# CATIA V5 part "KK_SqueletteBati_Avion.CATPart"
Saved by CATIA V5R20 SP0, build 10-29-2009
Part number: Squelette_bati_(avion)
Bounding box of the stored display mesh (mm): x -2696 to 0, y -488 to 1576, z -320 to 600
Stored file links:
  G:\Khaled_CFAO_2011\ST2M\ST2M_GR2\aboulegue\Khaled\CAD_thinkMOTION\KK_SqueletteBati_Avion.CATPart
  G:\Khaled_CFAO_2011\ST2M\ST2M_GR2\aboulegue\Khaled\CAD_thinkMOTION\KK_Train_Atterrissage.CATProduct
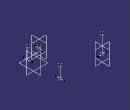
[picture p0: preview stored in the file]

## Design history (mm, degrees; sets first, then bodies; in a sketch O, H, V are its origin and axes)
Set1
  Point1 "Point.25": linked copy from another document
  Point2 "Point.22": linked copy from another document
  Point3 "Point.26": linked copy from another document
  Point4 "Point.23": linked copy from another document
  Point5 "Point.24": linked copy from another document
  Point6 "Point.11": linked copy from another document
  Plane1 "Plan reference 2": linked copy from another document
  Point7 "Point.27": linked copy from another document
  Point8 "Point.18": linked copy from another document
  Plane2 "Plan reference": linked copy from another document
Set2 "Set bati (avion)"
  Line1: type PtPt, FirstPoint Point1, SecondPoint Point2
  Line2: type PtPt, FirstPoint Point3, SecondPoint Point4
  Line3: type PtPt, FirstPoint Point5, SecondPoint Point6
  Line4: type Normal, RefPoint Point6, RefSkin Plane1, Start -200, End 200
  Line5: type Normal, RefPoint Point2, RefSkin Plane1, Start -200, End 200
  Line6: type Normal, RefPoint Point4, RefSkin Plane1, Start -200, End 200
  Line7: type PtPt, FirstPoint Point7, SecondPoint Point8
  Line8: type Normal, RefPoint Point8, RefSkin Plane2, Start -200, End 200
  Plane3 "Plan bati 1": type 2Lines, Element1 Line3, Element2 Line4
  Plane4 "Plan bati 2": type Angle, RefPlane Plane3, Direction Line3, Angle 90
  Plane5 "Plan bati 3": type 2Lines, Element1 Line8, Element2 Line7
  Plane6 "Plan bati 4": type Angle, RefPlane Plane5, Direction Line7, Angle 90
Body1 (main body)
